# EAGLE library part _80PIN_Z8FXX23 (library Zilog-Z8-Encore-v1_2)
Z8 Encore, QFP-80 Package
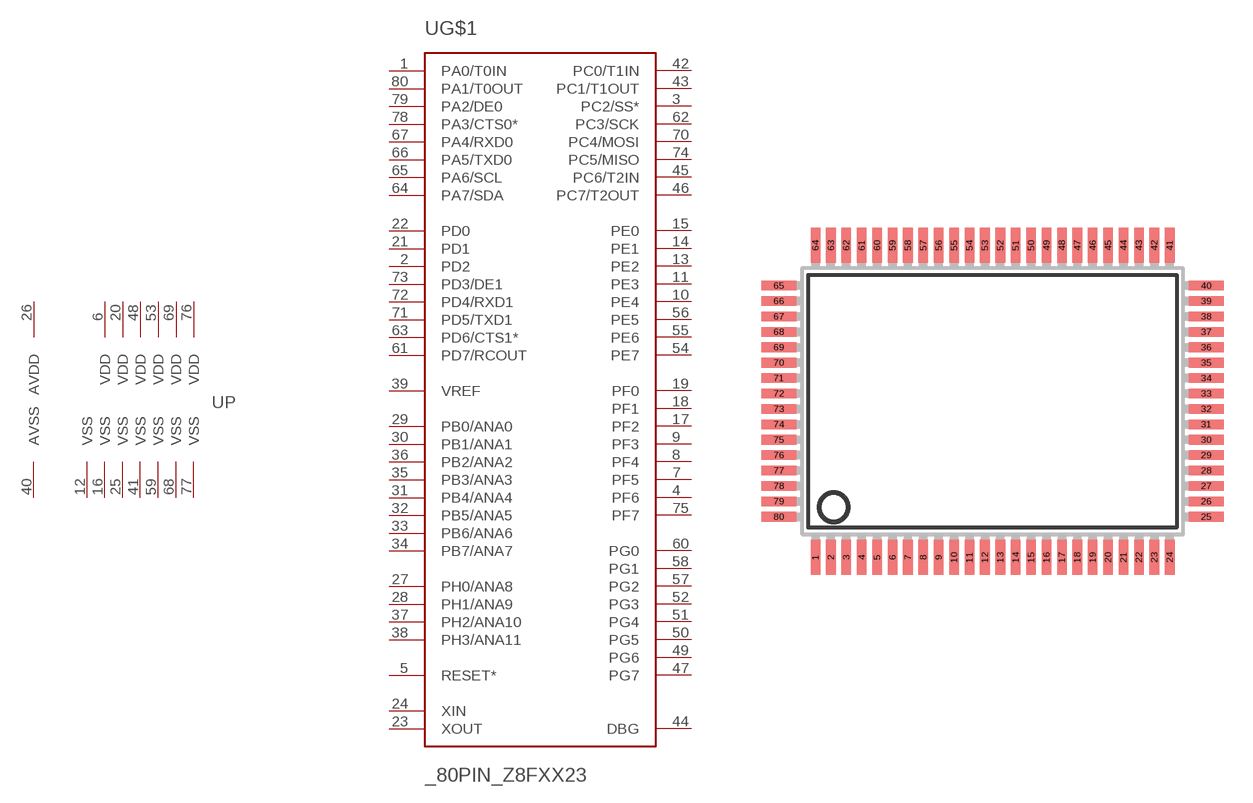
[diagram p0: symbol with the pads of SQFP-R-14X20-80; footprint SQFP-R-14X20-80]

Designator prefix U; gates G$1=Z8FXX23 P=PWR_80-PIN

## _80PIN_Z8FXX23FT  [SQFP-R-14X20-80]
1  G$1:PA0/T0IN
2  G$1:PD2
3  G$1:PC2/SS*
4  G$1:PF6
5  G$1:RESET*  in
6  P:VDD  pwr
7  G$1:PF5
8  G$1:PF4
9  G$1:PF3
10  G$1:PE4
11  G$1:PE3
12  P:VSS  pwr
13  G$1:PE2
14  G$1:PE1
15  G$1:PE0
16  P:VSS  pwr
17  G$1:PF2
18  G$1:PF1
19  G$1:PF0
20  P:VDD  pwr
21  G$1:PD1
22  G$1:PD0
23  G$1:XOUT  out
24  G$1:XIN  in
25  P:VSS  pwr
26  P:AVDD  pwr
27  G$1:PH0/ANA8
28  G$1:PH1/ANA9
29  G$1:PB0/ANA0
30  G$1:PB1/ANA1
31  G$1:PB4/ANA4
32  G$1:PB5/ANA5
33  G$1:PB6/ANA6
34  G$1:PB7/ANA7
35  G$1:PB3/ANA3
36  G$1:PB2/ANA2
37  G$1:PH2/ANA10
38  G$1:PH3/ANA11
39  G$1:VREF  pas
40  P:AVSS  pwr
41  P:VSS  pwr
42  G$1:PC0/T1IN
43  G$1:PC1/T1OUT
44  G$1:DBG
45  G$1:PC6/T2IN
46  G$1:PC7/T2OUT
47  G$1:PG7
48  P:VDD  pwr
49  G$1:PG6
50  G$1:PG5
51  G$1:PG4
52  G$1:PG3
53  P:VDD  pwr
54  G$1:PE7
55  G$1:PE6
56  G$1:PE5
57  G$1:PG2
58  G$1:PG1
59  P:VSS  pwr
60  G$1:PG0
61  G$1:PD7/RCOUT
62  G$1:PC3/SCK
63  G$1:PD6/CTS1*
64  G$1:PA7/SDA
65  G$1:PA6/SCL
66  G$1:PA5/TXD0
67  G$1:PA4/RXD0
68  P:VSS  pwr
69  P:VDD  pwr
70  G$1:PC4/MOSI
71  G$1:PD5/TXD1
72  G$1:PD4/RXD1
73  G$1:PD3/DE1
74  G$1:PC5/MISO
75  G$1:PF7
76  P:VDD  pwr
77  P:VSS  pwr
78  G$1:PA3/CTS0*
79  G$1:PA2/DE0
80  G$1:PA1/T0OUT

## Footprint SQFP-R-14X20-80 (pad centres in mm)
QFP-80 shrink quad flat pack, rectangle
smd 0.5 x 1.8: 1 -9.2,-8.1; 2 -8.4,-8.1; 3 -7.6,-8.1; 4 -6.8,-8.1; 5 -6,-8.1; 6 -5.2,-8.1; 7 -4.4,-8.1; 8 -3.6,-8.1; 9 -2.8,-8.1; 10 -2,-8.1; 11 -1.2,-8.1; 12 -0.4,-8.1; 13 0.4,-8.1; 14 1.2,-8.1; 15 2,-8.1; 16 2.8,-8.1; 17 3.6,-8.1; 18 4.4,-8.1; 19 5.2,-8.1; 20 6,-8.1; 21 6.8,-8.1; 22 7.6,-8.1; 23 8.4,-8.1; 24 9.2,-8.1; 41 9.2,8.1; 42 8.4,8.1; 43 7.6,8.1; 44 6.8,8.1; 45 6,8.1; 46 5.2,8.1; 47 4.4,8.1; 48 3.6,8.1; 49 2.8,8.1; 50 2,8.1; 51 1.2,8.1; 52 0.4,8.1; 53 -0.4,8.1; 54 -1.2,8.1; 55 -2,8.1; 56 -2.8,8.1; 57 -3.6,8.1; 58 -4.4,8.1; 59 -5.2,8.1; 60 -6,8.1; 61 -6.8,8.1; 62 -7.6,8.1; 63 -8.4,8.1; 64 -9.2,8.1
smd 1.8 x 0.5: 25 11.1,-6; 26 11.1,-5.2; 27 11.1,-4.4; 28 11.1,-3.6; 29 11.1,-2.8; 30 11.1,-2; 31 11.1,-1.2; 32 11.1,-0.4; 33 11.1,0.4; 34 11.1,1.2; 35 11.1,2; 36 11.1,2.8; 37 11.1,3.6; 38 11.1,4.4; 39 11.1,5.2; 40 11.1,6; 65 -11.1,6; 66 -11.1,5.2; 67 -11.1,4.4; 68 -11.1,3.6; 69 -11.1,2.8; 70 -11.1,2; 71 -11.1,1.2; 72 -11.1,0.4; 73 -11.1,-0.4; 74 -11.1,-1.2; 75 -11.1,-2; 76 -11.1,-2.8; 77 -11.1,-3.6; 78 -11.1,-4.4; 79 -11.1,-5.2; 80 -11.1,-6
